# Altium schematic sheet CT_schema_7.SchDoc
size 371 x 245 mm
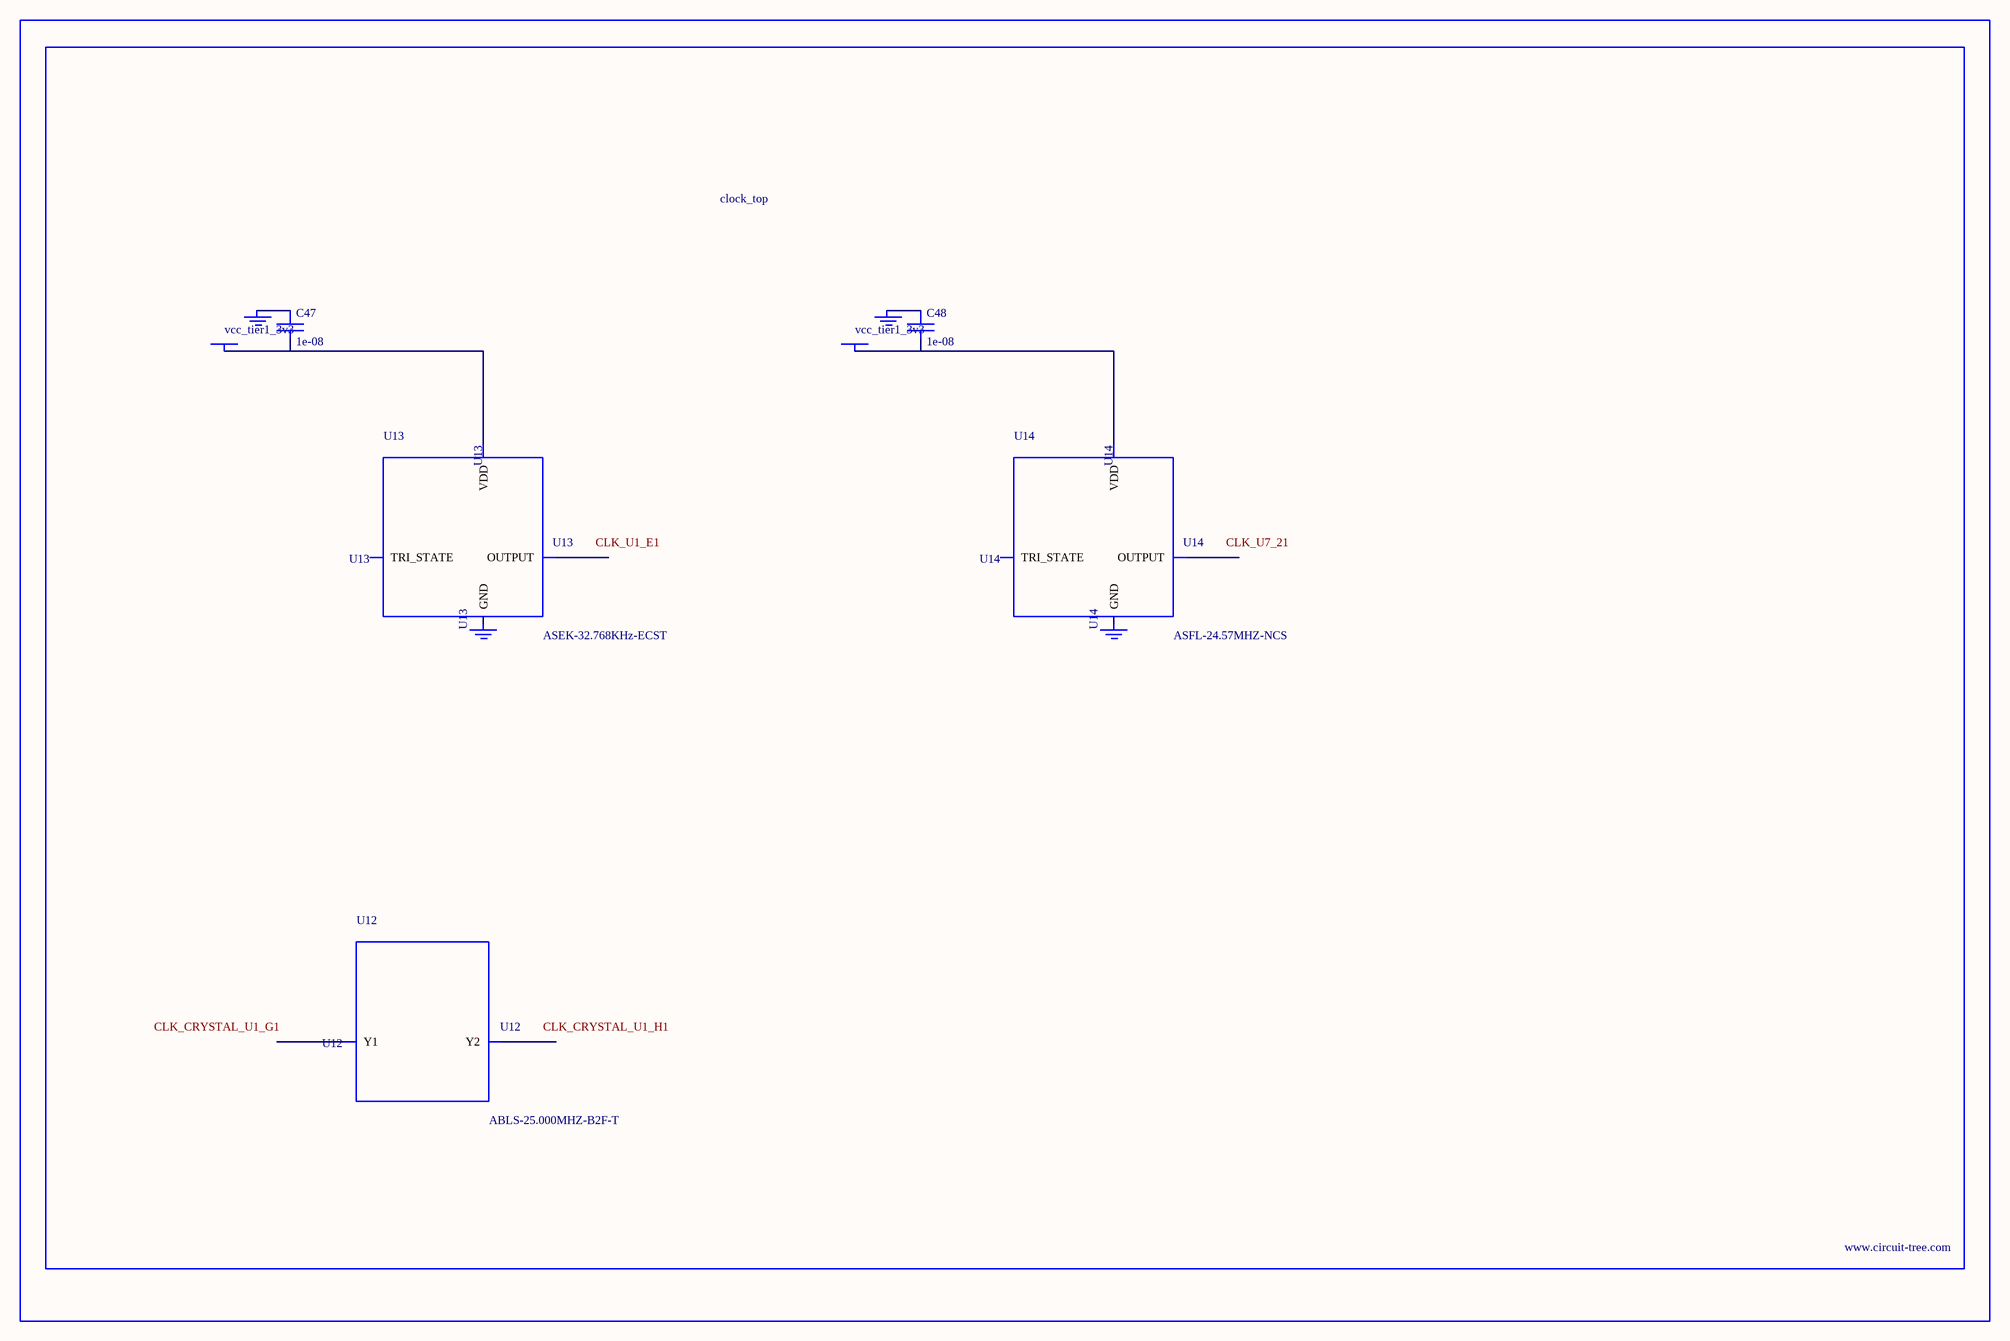
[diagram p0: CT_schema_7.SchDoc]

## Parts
BORDER6  (no value)
C47  1e-08  [C0402]
C48  1e-08  [C0402]
GND_INSTANCE_6_0  (no value)
GND_INSTANCE_6_1  (no value)
GND_INSTANCE_6_2  (no value)
GND_INSTANCE_6_3  (no value)
POWER_INSTANCE_6_0  vcc_tier1_3v3
POWER_INSTANCE_6_1  vcc_tier1_3v3
U12  ABLS-25.000MHZ-B2F-T  [ABLS-25.000MHZ-B2F-T]
U13  ASEK-32.768KHz-ECST  [ASEK]
U14  ASFL-24.57MHZ-NCS  [ASFL1]

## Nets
NetC47_1: C47.1 GND_INSTANCE_6_0.0(GND)
NetC47_2: C47.2 POWER_INSTANCE_6_0.0(PWR) U13.4(VDD)
NetC48_1: C48.1 GND_INSTANCE_6_2.0(GND)
NetC48_2: C48.2 POWER_INSTANCE_6_1.0(PWR) U14.4(VDD)

Not connected (* = marked no-connect by the designer): GND_INSTANCE_6_1 0(GND); GND_INSTANCE_6_3 0(GND); U12 1(Y1) 2(Y2); U13 1(TRI_STATE) 2(GND) 3(OUTPUT); U14 1(TRI_STATE) 2(GND) 3(OUTPUT)

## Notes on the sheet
- Labels drawn without touching a wire or pin: CLK_CRYSTAL_U1_G1, CLK_CRYSTAL_U1_H1, CLK_U1_E1, CLK_U7_21

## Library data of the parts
BORDER6 = BORDER_PAGE6
C47 C48 = C0402C103K3RAC
GND_INSTANCE_6_0-GND_INSTANCE_6_3 = GND
POWER_INSTANCE_6_0 POWER_INSTANCE_6_1 = PWR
